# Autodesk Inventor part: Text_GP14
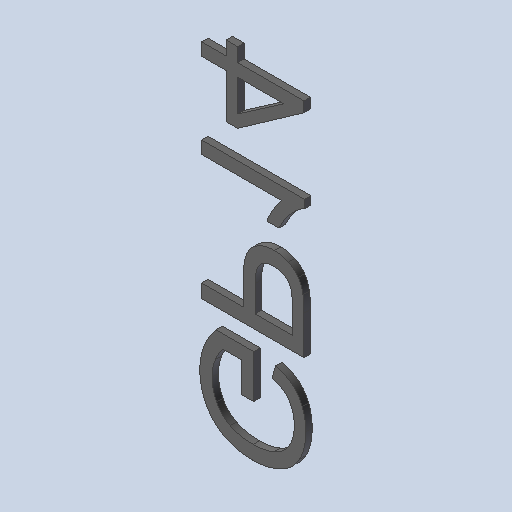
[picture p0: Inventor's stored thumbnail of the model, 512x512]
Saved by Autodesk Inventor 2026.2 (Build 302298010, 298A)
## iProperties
Created: 2026-10
Part Number: Text_GP14
Material: Générique
Document SubType Name: Modeling
Designer: mel
Density: 1 g/cm^3
Appearance: Par défaut
Author: mel
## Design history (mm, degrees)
feature "Base1"
feature "Base2"
feature "Base3"
feature "Base4"
node "Solide1"
node "Solide2"
node "Solide3"
node "Solide4"
